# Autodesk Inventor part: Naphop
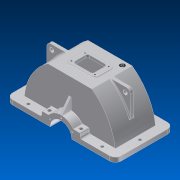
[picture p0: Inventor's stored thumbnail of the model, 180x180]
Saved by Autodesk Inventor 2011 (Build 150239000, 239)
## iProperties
Created: 2011-05
Part Number: Naphop
Document SubType Name: Modeling
Designer: 904Chiaki
Density: 1 g/cm^3
Mass: 4979.46 g
Surface Area: 8180.21 cm^2
Volume: 4979.46 cm^3
Author: 904Chiaki
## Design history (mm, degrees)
node "Blocks"
  sketch "Block1"
    geometry: L1 (249.664, 121.924)-(249.664, 66.924); L2 (274.664, 124.424)-(274.664, 64.424); L3 (159.664, 131.924)-(239.664, 131.924); L4 (239.664, 56.924)-(159.664, 56.924); L5 (144.664, 144.424)-(254.664, 144.424); L6 (254.664, 44.424)-(144.664, 44.424); L7 (149.664, 66.924)-(149.664, 121.924); L8 (124.664, 64.424)-(124.664, 124.424); A1 r 10 centre (239.664, 66.924) between (239.664, 56.924) and (249.664, 66.924); A2 r 10 centre (239.664, 121.924) between (249.664, 121.924) and (239.664, 131.924); A3 r 20 centre (254.664, 124.424) between (274.664, 124.424) and (254.664, 144.424); A4 r 10 centre (159.664, 121.924) between (159.664, 131.924) and (149.664, 121.924); A5 r 10 centre (159.664, 66.924) between (149.664, 66.924) and (159.664, 56.924); A6 r 20 centre (144.664, 124.424) between (144.664, 144.424) and (124.664, 124.424); A7 r 20 centre (144.664, 64.424) between (124.664, 64.424) and (144.664, 44.424); A8 r 20 centre (254.664, 64.424) between (254.664, 44.424) and (274.664, 64.424); 1 further point
    constraints: 16 end point, 16 point on circle, 8 centre point
    dimensions: "d73" = 150 distance between parallel lines of L2 L8; "d74" = 100 distance between parallel lines of L6 L5; "d75" = 100 distance between parallel lines of L1 L7; "d76" = 75 distance between parallel lines of L4 L3; "d77" = 25 distance between parallel lines of L2 L1; "d78" = 12.5 distance between parallel lines of L6 L4
sketch "Sketch1"
  geometry: L1 (-32.336, 188.411)-(431.664, 188.411); L2 (431.664, 188.411)-(431.664, -16.589); L3 (431.664, -16.589)-(-32.336, -16.589); L4 (-32.336, -16.589)-(-32.336, 188.411); 2 further points
  constraints: 8 end point, 1 horizontal, 1 vertical
  dimensions: "d0" = 205 distance of L1.end L2.end; "d1" = 464 distance of L1.start L1.end; "d2" = 464 distance of L2.end L3.end; "d3" = 205 distance of L3.end L1.start
extrude "Extrusion1" new body sketch "Sketch1" distance "d4" = 227; taper "d5" = 0 deg
sketch "Sketch9"
  geometry: L1 (464, 227)-(0, 227) reference; L2 (0, 0)-(0, 227) reference; L3 (464, 0)-(464, 227) reference; L4 (464, 227)-(464, 0); L5 (0, 0)-(0, 227); L6 (0, 227)-(120, 227); L7 (344, 227)-(464, 227); A1 r 294.198 centre (169.98, -10.211) between (464, 0) and (344, 227); A2 r 274.704 centre (274.704, 0) between (120, 227) and (0, 0); 1 further point
  constraints: 8 end point, 4 point on circle, 2 centre point, 2 point on line
  dimensions: "d43" = 120 distance from line of L3 L7.start; "d44" = 120 distance from line of L2 L6.end
extrude "Extrusion8" cut sketch "Sketch9" stored distance "d47" = 4; taper "d48" = 0 deg
shell "Shell2" dims "d49" = 10
sketch "Sketch10"
  geometry: L1 (464, 0)-(0, 0) reference; C1 r 55 at (232, 0); 1 further point
  constraints: 1 centre point, 1 midpoint
  dimensions: "d50" = 110 diameter of C1
extrude "Extrusion9" cut sketch "Sketch10" stored distance "d51" = 4; taper "d52" = 0 deg
sketch "Sketch11"
  geometry: L1 (344, -227)-(167, -227) reference; L2 (57, -227)-(-120, -227) reference; L3 (191, -227)-(167, -227); L4 (57, -227)-(33, -227); A1 r 55 centre (112, -227) between (167, -227) and (57, -227) reference; A2 r 79 centre (112, -227) between (191, -227) and (33, -227); A3 r 55 centre (112, -227) between (167, -227) and (57, -227); 1 further point
  constraints: 4 end point, 4 point on circle, 2 centre point, 2 coincident, 2 point on line
  dimensions: "d53" = 158 diameter of A2
extrude "Extrusion10" join sketch "Sketch11" distance "d54" = 45; taper "d55" = 0 deg
sketch "Sketch12"
  geometry: L1 (-113.115, 217)-(53.885, 217) reference; L2 (163.885, 217)-(330.879, 217) reference; L3 (187.885, 217)-(163.885, 217); L4 (53.885, 217)-(29.885, 217); A1 r 55 centre (108.885, 217) between (53.885, 217) and (163.885, 217) reference; A2 r 79 centre (108.885, 217) between (29.885, 217) and (187.885, 217); A3 r 55 centre (108.885, 217) between (53.885, 217) and (163.885, 217); 1 further point
  constraints: 4 end point, 4 point on circle, 2 centre point, 2 coincident, 2 point on line
  dimensions: "d56" = 158 diameter of A2
extrude "Extrusion11" join sketch "Sketch12" distance "d57" = 10; taper "d58" = 0 deg
chamfer "Chamfer2" distance "d59" = 10; stored, may be unused: second distance "d60" = 15, angle "d61" = 45 deg
workplane "Work Plane2"
mirror "Mirror3"
sketch "Sketch13"
  geometry: L1 (-144.664, 3.411)-(-144.664, -61.589) reference; L2 (32.336, -16.589)-(32.336, 188.411) reference; L3 (-144.664, 168.411)-(-144.664, 233.411) reference; L4 (-120.664, 178.411)-(22.336, 178.411) reference; L5 (22.336, 178.411)-(22.336, -6.589) reference; L6 (22.336, -6.589)-(-120.664, -6.589) reference; L7 (-278.664, -6.589)-(-263.664, 3.411) reference; L8 (-278.664, -6.589)-(-421.658, -6.589) reference; L9 (-421.658, -6.589)-(-421.658, 178.411) reference; L10 (-421.658, 178.411)-(-278.664, 178.411) reference; L11 (-278.664, 178.411)-(-263.664, 168.411) reference; L12 (-254.664, 168.411)-(-263.664, 168.411) reference; L13 (-254.664, 168.411)-(-254.664, 233.411) reference; L14 (-278.664, 233.411)-(-254.664, 233.411) reference; L15 (-278.664, 188.411)-(-278.664, 233.411) reference; L16 (-278.664, 188.411)-(-431.664, 188.411) reference; L17 (-431.664, 188.411)-(-431.664, -16.589) reference; L18 (-431.664, -16.589)-(-278.664, -16.589) reference; L19 (-278.664, -16.589)-(-278.664, -61.589) reference; L20 (-278.664, -61.589)-(-254.664, -61.589) reference; L21 (-254.664, -61.589)-(-254.664, 3.411) reference; L22 (-254.664, 3.411)-(-263.664, 3.411) reference; L23 (77.336, 233.411)-(77.336, -61.589); L24 (-476.664, -61.589)-(-476.664, 233.411); L25 (-120.664, -6.589)-(-144.664, -6.589); L26 (-254.664, -6.589)-(-278.664, -6.589); L27 (77.336, -61.589)-(-144.664, -61.589); L28 (-254.664, -61.589)-(-476.664, -61.589); L29 (-120.664, 178.411)-(-144.664, 178.411); L30 (-254.664, 178.411)-(-278.664, 178.411); L31 (-476.664, 233.411)-(-254.664, 233.411); L32 (-144.664, 233.411)-(77.336, 233.411); 1 further point
  constraints: 24 end point, 4 point on line
  dimensions: "d64" = 45 distance between parallel lines of L2 L23; "d66" = 45 distance between parallel lines of L17 L24
extrude "Extrusion12" join sketch "Sketch13" distance "d67" = 23; taper "d68" = 0 deg
fillet "Fillet2" dims "d69" = 30
fillet "Fillet3" dims "d70" = 30
sketch "Sketch14"
  geometry: L1 (87.664, 188.411)-(87.664, -16.589) reference; L2 (87.664, 188.411)-(311.664, 188.411) reference; 2 further points
  dimensions: "d71" = 224 distance of L1.start L2.end (derived); "d72" = 205 distance of L1.start L1.end (derived); "d79" = 37 dimension on L1; "d80" = 52.5 dimension on L2
extrude "Extrusion13" join sketch "Sketch14" distance "d81" = 4; taper "d82" = 0 deg
sketch "Sketch15"
  geometry: L1 (249.664, 58.411)-(249.664, 113.411) reference; L2 (239.664, 123.411)-(159.664, 123.411) reference; L3 (149.664, 113.411)-(149.664, 58.411) reference; L4 (159.664, 48.411)-(239.664, 48.411) reference; A1 r 10 centre (239.664, 113.411) between (249.664, 113.411) and (239.664, 123.411) reference; A2 r 10 centre (159.664, 113.411) between (159.664, 123.411) and (149.664, 113.411) reference; A3 r 10 centre (159.664, 58.411) between (149.664, 58.411) and (159.664, 48.411) reference; A4 r 10 centre (239.664, 58.411) between (239.664, 48.411) and (249.664, 58.411) reference; 1 further point
extrude "Extrusion14" cut sketch "Sketch15" stored distance "d83" = 4; taper "d84" = 0 deg
fillet "Fillet4" dims "d85" = 2
sketch "Sketch16"
  geometry: L1 (-247, -23)-(-75.578, -23) reference; L2 (75.578, -23)-(247, -23) reference; L3 (-97.746, -48)-(-62.746, -48); L4 (62.746, -48)-(97.746, -48); L5 (97.746, -48)-(97.746, -23); L6 (-97.746, -48)-(-97.746, -23); A1 r 79 centre (0, 0) between (-75.578, -23) and (75.578, -23) reference; 1 further point
  constraints: 8 end point, 2 point on circle, 2 point on line
  dimensions: "d87" = 35 distance from line of L4.start L5; "d88" = 35 distance from line of L3.end L6
extrude "Extrusion15" join sketch "Sketch16" stored distance "d89" = 4; taper "d90" = 0 deg
mirror "Mirror4"
workplane "Work Plane3"
  workaxis "Work Axis1"
sketch "Sketch17"
  geometry: L1 (-250, 79)-(-205, 139); L2 (-250, 79)-(-250, 70.744); 1 further point
  constraints: 4 end point
  dimensions: "d92" = 60 vertical distance of L1.start L1.end
feature "Rib1" sketch "Sketch17" dims "d93" = 1, "d94" = 10, "d95" = 0
mirror "Mirror5"
fillet "Fillet5" dims "d96" = 10
sketch "Sketch18"
  geometry: L1 (209.746, -194)-(209.746, -179) reference; L2 (209.746, -179)-(174.746, -179) reference; L3 (117, -148.158)-(117, -88) reference; L4 (117, -88)-(107, -88) reference; L5 (107, -88)-(107, -148.158) reference; L6 (49.254, -179)-(14.254, -179) reference; L7 (14.254, -179)-(14.254, -194) reference; L8 (4.254, -204)-(-119.035, -204) reference; L9 (0, 0)-(224, 0) reference; L10 (342.297, -204)-(219.746, -204) reference; L11 (0, 0)-(-80, 0); L12 (-100, -20)-(-100, -124.101); C1 r 10 at (-75, -25); A1 r 10 centre (219.746, -194) between (209.746, -194) and (219.746, -204) reference; A2 r 79 centre (112, -227) between (174.746, -179) and (117, -148.158) reference; A3 r 79 centre (112, -227) between (107, -148.158) and (49.254, -179) reference; A4 r 10 centre (4.254, -194) between (4.254, -204) and (14.254, -194) reference; A5 r 274.704 centre (154.704, -227) between (0, 0) and (-119.035, -204) reference; A6 r 294.198 centre (49.98, -237.211) between (342.297, -204) and (224, 0) reference; A7 r 20 centre (-80, -20) between (-80, 0) and (-100, -20); 2 further points
  constraints: 4 end point, 3 point on circle, 2 centre point, 2 point on line, 2 tangent
  dimensions: "d98" = 100 distance of L9.start point (-100, 0); "d99" = 20 radius of A7; "d100" = 20 diameter of C1; "d101" = 25 distance from line of L11 C1.centre; "d102" = 25 distance from line of L12 C1.centre
extrude "Extrusion16" join sketch "Sketch18" stored distance "d103" = 15; taper "d104" = 0 deg
fillet "Fillet7" dims "d105" = 5
sketch "Sketch19"
  geometry: L1 (209.746, -194)-(209.746, -179) reference; L2 (209.746, -179)-(174.746, -179) reference; L3 (117, -148.158)-(117, -88) reference; L4 (117, -88)-(107, -88) reference; L5 (107, -88)-(107, -148.158) reference; L6 (49.254, -179)-(14.254, -179) reference; L7 (14.254, -179)-(14.254, -194) reference; L8 (4.254, -204)-(-119.035, -204) reference; L9 (0, 0)-(224, 0) reference; L10 (342.297, -204)-(219.746, -204) reference; L11 (224, 0)-(304, 0); L12 (324, -20)-(324, -130.136); C1 r 10 at (299, -25); A1 r 10 centre (219.746, -194) between (209.746, -194) and (219.746, -204) reference; A2 r 79 centre (112, -227) between (174.746, -179) and (117, -148.158) reference; A3 r 79 centre (112, -227) between (107, -148.158) and (49.254, -179) reference; A4 r 10 centre (4.254, -194) between (4.254, -204) and (14.254, -194) reference; A5 r 274.704 centre (154.704, -227) between (0, 0) and (-119.035, -204) reference; A6 r 294.198 centre (49.98, -237.211) between (342.297, -204) and (224, 0) reference; A7 r 20 centre (304, -20) between (324, -20) and (304, 0); 2 further points
  constraints: 4 end point, 3 point on circle, 2 centre point, 2 point on line, 2 tangent
  dimensions: "d106" = 100 distance of L9.end point (324, 0); "d107" = 20 radius of A7; "d108" = 20 diameter of C1; "d109" = 25 distance from line of L11 C1.centre; "d110" = 25 distance from line of L12 C1.centre
extrude "Extrusion17" join sketch "Sketch19" stored distance "d111" = 15; taper "d112" = 0 deg
fillet "Fillet8" dims "d113" = 5
fillet "Fillet9" dims "d114" = 1
workpoint "Work Point1"
workpoint "Work Point2"
workpoint "Work Point3"
workpoint "Work Point4"
workpoint "Work Point5"
workpoint "Work Point6"
workpoint "Work Point7"
workpoint "Work Point8"
workpoint "Work Point9"
workpoint "Work Point10"
workpoint "Work Point11"
workpoint "Work Point12"
fillet "Fillet11" dims "d122" = 5
fillet "Fillet12" dims "d123" = 5
fillet "Fillet13" dims "d124" = 2
node "Hole2"
node "Hole4"
hole "Hole5" diameter "d141" = 4; stored, may be unused: countersink angle "d145" = 90 deg, drill point angle "d147" = 118 deg; dims "d139" = 10, "d140" = 10, "d142" = 6, "d143" = 4, "d144" = 2, "d146" = 8
hole "Hole6" diameter "d150" = 4; stored, may be unused: countersink angle "d154" = 90 deg, drill point angle "d156" = 118 deg; dims "d148" = 10, "d149" = 10, "d151" = 6, "d152" = 4, "d153" = 2, "d155" = 8
node "Hole8"
node "Hole10"
node "Hole12"
sketch "Sketch27"
  geometry: L1 (87.664, 188.411)-(311.664, 188.411) reference; L2 (311.664, 98.411)-(311.664, 188.411) reference; C1 r 6 at (286.664, 163.411); 1 further point
  constraints: 1 centre point
  dimensions: "d179" = 12 diameter of C1; "d180" = 25 distance from line of L2 C1.centre; "d181" = 25 distance from line of L1 C1.centre
extrude "Extrusion18" cut sketch "Sketch27" stored distance "d182" = 10; taper "d183" = 0 deg
sketch "Sketch28"
  geometry: C1 r 6 at (286.664, 163.411) reference; C2 r 12.5 at (286.664, 163.411); 1 further point
  constraints: 1 centre point, 1 coincident
  dimensions: "d184" = 25 diameter of C2
extrude "Extrusion19" join sketch "Sketch28" distance "d185" = 2; taper "d186" = 0 deg
fillet "Fillet14" dims "d187" = 2
thread "Thread1" dims "d188" = 10, "d189" = 0
body "Solid1"
node "Projected Loop2"
node "Projected Loop3"
node "Projected Loop4"
sketch "Sketch22"
  geometry: 4 further points
hole "Hole1" sketch "Sketch22" diameter "d125" = 17.5; stored, may be unused: countersink angle "d129" = 90 deg, drill point angle "d131" = 0 deg; dims "d126" = 6, "d127" = 4, "d128" = 2, "d130" = 8
sketch "Sketch23"
  geometry: 6 further points
hole "Hole3" sketch "Sketch23" diameter "d132" = 15.5; stored, may be unused: countersink angle "d136" = 90 deg, drill point angle "d138" = 0 deg; dims "d133" = 6, "d134" = 4, "d135" = 2, "d137" = 8
sketch "Sketch24"
  geometry: 4 further points
hole "Hole7" sketch "Sketch24" diameter "d157" = 8.376; stored, may be unused: countersink angle "d161" = 90 deg, drill point angle "d163" = 120 deg; dims "d158" = 21, "d159" = 4, "d160" = 2, "d162" = 26
sketch "Sketch25"
  geometry: 6 further points
hole "Hole9" sketch "Sketch25" diameter "d164" = 8.376; stored, may be unused: countersink angle "d168" = 90 deg, drill point angle "d170" = 120 deg; dims "d165" = 19, "d166" = 4, "d167" = 2, "d169" = 24
sketch "Sketch26"
  geometry: 6 further points
hole "Hole11" sketch "Sketch26" diameter "d171" = 8.376; stored, may be unused: countersink angle "d175" = 90 deg, drill point angle "d177" = 120 deg; dims "d172" = 19, "d173" = 4, "d174" = 2, "d176" = 24
node "Block1:1" dims "d79" = 37, "d80" = 52.5
other parameters: "d20" = 45, "d22" = 45, "d62" = -102.5, "d63" = 45, "d65" = 45, "d86" = 25, "d91" = 0
